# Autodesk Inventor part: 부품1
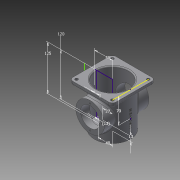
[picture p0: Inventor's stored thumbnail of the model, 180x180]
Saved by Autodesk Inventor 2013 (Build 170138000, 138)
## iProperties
Created: 2015-10
Part Number: 부품1
Material: 일반
Document SubType Name: Modeling
Designer: Administrator
Density: 1 g/cm^3
Author: Administrator
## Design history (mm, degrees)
sketch "스케치1"
  geometry: L1 (0, 0)-(50, 0); L2 (78.014, 0)-(78.014, -40); L3 (50, -40)-(50, -120); L4 (0, -125)-(0, 0); L5 (40, -120)-(40, -125); L6 (40, -125)-(0, -125); L7 (40, -125)-(40, -120); L8 (40, -120)-(50, -120); L9 (50, -40)-(50, 0); L10 (27, -125)-(27, -112); L11 (27, -112)-(45, -112); L12 (45, -112)-(45, 0)
  constraints: 24 end point, 7 perpendicular, 4 parallel, 2 point on line, 1 horizontal
  dimensions: "d0" = 50 distance between parallel lines of L4 L3; "d2" = 40 distance between parallel lines of L4 L7; "d4" = 125 distance between parallel lines of L1 L6; "d5" = 120 distance between parallel lines of L1 L8; "d6" = 27 distance between parallel lines of L4 L10; "d7" = 13 distance between parallel lines of L10 L5 (derived); "d8" = 13 distance between parallel lines of L11 L6; "d9" = 5 distance between parallel lines of L12 L3
revolve "회전1" stored, may be unused: angle "d10" = 90 deg
sketch "스케치3"
  geometry: L1 (-60, 60)-(60, 60); L2 (60, 60)-(60, -60); L3 (60, -60)-(-60, -60); L4 (-60, -60)-(-60, 60); C1 r 50 at (0, 0) reference; 2 further points
  constraints: 8 end point, 2 midpoint, 2 parallel, 1 horizontal, 1 horizontal alignment, 1 perpendicular, 1 vertical alignment
  dimensions: "d15" = 120 distance of L1.end L2.end; "d17" = 120 distance of L1.start L1.end
extrude "돌출1" join sketch "스케치3" distance "d18" = 10; taper "d19" = 0 deg
node "작업 평면1"
sketch "스케치4"
  geometry: C1 r 40 at (0, -60); 1 further point
  constraints: 1 centre point, 1 vertical alignment
  dimensions: "d21" = 80 diameter of C1; "d23" = 60 distance of point (0, 0) C1.centre
extrude "돌출2" join sketch "스케치4" distance "d24" = 124; taper "d25" = 0 deg
hole "구멍1" diameter "d28" = 54; stored, may be unused: countersink angle "d32" = 90 deg, drill point angle "d34" = 118 deg; dims "d26" = 10, "d27" = 10, "d29" = 6, "d30" = 4, "d31" = 2, "d33" = 8
fillet "모깎기1" dims "d35" = 10
fillet "모깎기2" dims "d36" = 3
sketch "스케치5"
  geometry: C1 r 40 at (0, 0) reference; A1 r 32.5 centre (0, 0) between (0, 32.5) and (-32.5, 0); 3 further points
  constraints: 4 point on circle, 1 centre point, 1 coincident
  dimensions: "d37" = 65 diameter of A1
sketch "스케치6"
  geometry: C1 r 40 at (0, 0) reference; A1 r 32.5 centre (0, 0) between (0, 32.5) and (0, -32.5); 3 further points
  constraints: 4 point on circle, 1 centre point, 1 coincident
  dimensions: "d39" = 65 diameter of A1
hole "구멍2" sketch "스케치5" diameter "d41" = 3.459; stored, may be unused: countersink angle "d45" = 90 deg, drill point angle "d47" = 118 deg; dims "d42" = 8, "d43" = 4, "d44" = 2, "d46" = 10
hole "구멍3" sketch "스케치6" diameter "d48" = 3.459; stored, may be unused: countersink angle "d52" = 90 deg, drill point angle "d54" = 118 deg; dims "d49" = 8, "d50" = 4, "d51" = 2, "d53" = 10
sketch "스케치7"
  geometry: C1 r 4 at (0, 110); C2 r 4 at (100, 110); C3 r 4 at (100, 10); C4 r 4 at (0, 10); A1 r 10 centre (0, 10) between (-10, 10) and (0, 0) reference; A2 r 10 centre (100, 10) between (100, 0) and (110, 10) reference; A3 r 10 centre (100, 110) between (110, 110) and (100, 120) reference; A4 r 10 centre (0, 110) between (0, 120) and (-10, 110) reference
  constraints: 4 centre point, 4 coincident
  dimensions: "d55" = 8 diameter of C1; "d57" = 8 diameter of C2; "d58" = 8 diameter of C3; "d59" = 8 diameter of C4
extrude "돌출3" cut sketch "스케치7" distance "d60" = 124; taper "d61" = 0 deg
sketch "스케치8"
  geometry: L1 (-92.542, 0)-(92.542, 0); L2 (-56.585, -56.585)-(56.585, 56.585); L3 (98.99, -98.99)-(-98.99, 98.99); C1 r 27 at (0, 0) reference; C2 r 40 at (0, 0) reference; A1 r 32.5 centre (0, 0) between (-22.981, 22.981) and (-22.981, -22.981); 3 further points
  constraints: 6 end point, 4 point on circle, 4 point on line, 3 midpoint, 2 coincident, 1 centre point, 1 horizontal
  dimensions: "d62" = 65 diameter of A1; "d64" = 45 deg angle of L1 L2; "d66" = 45 deg angle of L3 L1
hole "구멍4" sketch "스케치8" at (-22.981, 22.981), (-22.981, -22.981), (22.981, -22.981), (22.981, 22.981) diameter "d68" = 3.459; stored, may be unused: countersink angle "d72" = 90 deg, drill point angle "d74" = 118 deg; dims "d69" = 8, "d70" = 4, "d71" = 2, "d73" = 10
fillet "모깎기3" dims "d75" = 5
fillet "모깎기4" dims "d76" = 5
fillet "모깎기5" dims "d77" = 5
revolve "회전2" stored, may be unused: angle "d78" = 90 deg
chamfer "모따기1" distance "d79" = 1; stored, may be unused: second distance "d80" = 2, angle "d81" = 45 deg
node "작업 평면2"
sketch "스케치9" dims "d62" = 65, "d64" = 45 deg, "d66" = 45 deg
  geometry: L1 (50, 0)-(-50, 0) reference; 3 further points
  constraints: 1 midpoint, 1 vertical alignment, 1 other
  dimensions: "d83" = 70 distance from line of L1 point (0, -70)
fillet "모깎기6" dims "d84" = 3
node "솔리드1"
other parameters: "d20" = 62
